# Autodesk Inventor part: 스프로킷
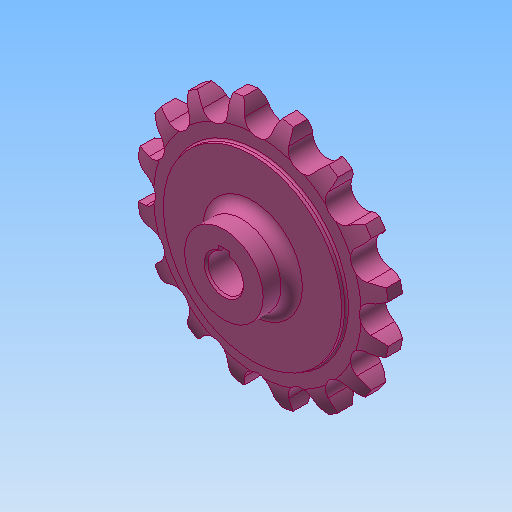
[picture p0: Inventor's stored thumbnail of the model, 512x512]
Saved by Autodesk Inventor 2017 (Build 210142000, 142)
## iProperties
Created: 2016-03
Part Number: 스프로킷
Material: 강철, 탄소
Document SubType Name: Modeling
Designer: mduedu
Density: 7.87 g/cm^3
Mass: 230.696 g
Surface Area: 96.4947 cm^2
Volume: 29.3133 cm^3
Appearance: 분홍색
Author: mduedu
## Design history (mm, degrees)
sketch "스케치1"
  geometry: L1 (0, 5)-(25, 5); L2 (25, 5)-(25, 4.1); L3 (25.5, 3.6)-(29.125, 3.6); L4 (35.5, 2)-(35.5, 0); L5 (35.5, 0)-(0, 0); L6 (0, 0)-(0, 5); L7 (0, -5)-(25, -5); L8 (25, -5)-(25, -4.1); L9 (25.5, -3.6)-(29.125, -3.6); L10 (35.5, -2)-(35.5, 0); L11 (0, 0)-(0, -5); A1 r 13.5 centre (29.125, -9.9) between (35.5, 2) and (29.125, 3.6); A2 r 13.5 centre (29.125, 9.9) between (29.125, -3.6) and (35.5, -2); A3 r 0.5 centre (25.5, 4.1) between (25, 4.1) and (25.5, 3.6); A4 r 0.5 centre (25.5, -4.1) between (25.5, -3.6) and (25, -4.1); 2 further points
  constraints: 22 end point, 8 point on circle, 6 symmetric about line, 5 tangent, 4 centre point, 4 parallel, 4 point on line, 1 equal radius, 1 horizontal, 1 perpendicular, 1 other
  dimensions: "d0" = 71 diameter of L4 L6; "d2" = 50 diameter of L2 L6; "d3" = 1.6 vertical distance of L4.start L3.end; "d4" = 3.6 distance from line of L4.end L3; "d5" = 5 distance between parallel lines of L5 L1; "d6" = 13.5 radius of A1; "d15" = 0.5 radius of A3
revolve "회전1" sketch "스케치1" stored, may be unused: angle "d7" = 90 deg
sketch "스케치2" dims "d8" = 57.16, "d11" = 71
  geometry: L1 (0, 0)-(0, 28.58); A1 r 32.55 centre (0, 0) between (-16.114, 28.281) and (0, 32.55); A2 r 3.97 centre (0, 32.55) between (-3.838, 31.533) and (0, 28.58); A3 r 12.7 centre (-16.114, 28.281) between (-3.838, 31.533) and (-5.392, 35.088); A4 r 12.7 centre (16.114, 28.281) between (5.392, 35.088) and (3.838, 31.533); A5 r 3.97 centre (0, 32.55) between (0, 28.58) and (3.838, 31.533); A6 r 35.5 centre (0, 0) between (5.392, 35.088) and (-5.392, 35.088); 2 further points
  constraints: 12 point on circle, 6 centre point, 4 coincident, 3 symmetric about line, 2 end point, 1 point on line, 1 tangent, 1 vertical, 1 vertical alignment, 7 other
  dimensions: "d10" = 65.1 diameter of A1; "d12" = 12.7 radius of A3
extrude "돌출1" cut sketch "스케치2" stored distance "d13" = 10; taper "d14" = 0 deg
sketch "스케치3"
  geometry: C1 r 11 at (0, 0); 1 further point
  constraints: 1 centre point, 1 coincident
  dimensions: "d19" = 22 diameter of C1
extrude "돌출2" join sketch "스케치3" distance "d20" = 8; taper "d21" = 0 deg
fillet "모깎기1" dims "d22" = 3
sketch "스케치4"
  geometry: L1 (-1.5, 0)-(1.5, 0); L2 (1.5, 0)-(1.5, 6.4); L3 (1.5, 6.4)-(-1.5, 6.4); L4 (-1.5, 6.4)-(-1.5, 0); C1 r 5 at (0, 0); 2 further points
  constraints: 8 end point, 2 coincident, 2 parallel, 1 centre point, 1 horizontal, 1 midpoint, 1 perpendicular
  dimensions: "d23" = 10 diameter of C1; "d25" = 3 distance of L2.end L3.end; "d26" = 6.4 distance of L1.end L2.end
extrude "돌출3" cut sketch "스케치4" stored distance "d27" = 8; taper "d28" = 0 deg
chamfer "모따기1" distance "d29" = 0.5; stored, may be unused: second distance "d30" = 2, angle "d31" = 45 deg
node "솔리드1"
pattern_circular "원형 패턴1" dims angle "d17" = 360 deg
